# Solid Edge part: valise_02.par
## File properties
Author: Bernard DUMAS
Template: Normal.par
Last saved by: FR026244
Revision: 13
Application: Solid Edge
Material: Bois, Frêne
Style de face: Jaune kaki
Style de remplissage: Liège
Style virtuel: Frêne verni
Coef. of Thermal Exp: 0.0
Thermal Conductivity: 0.0
Specific Heat: 0.0
Modulus of Elasticity: 0.0
Poission's Ratio: 0.0
Yield Stress: 0.0
Ultimate Stress: 0.0
Elongation: 0.0
Densité: 460.000 kg/m^3
Précision: 0.9900
Document Number: 02
Revision: a
Project Name: Slamson
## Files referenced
..\Valise_Salmson.asm
bD:\Documents and Settings\FR026244\Mes Documents\Bernard\Slamson\Valise-Salmson\Valise_Salmson.asm
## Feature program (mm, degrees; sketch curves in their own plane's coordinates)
sketch for "unnamed Protrusion 1" plane through (0, 0, 0) normal (0, -1, 0) x-axis (1, 0, 0)
extrude "unnamed Protrusion 1" add to key point symmetric
extrude "unnamed Cutout 1" cut finite 6
extrude "Enlèvement_matière_2" cut finite 6
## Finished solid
Body 1: solid body, 10 faces, 24 edges, 16 vertices.
  Faces by surface: plane 10
  Edges by curve: line 24
Bounding box of the edges (mm): 6.000 x 850.000 x 103.000, from (0, -425, 3) to (6, 425, 106).
Planar faces by outward normal: +x 3, +y 2, +z 1, -x 1, -y 2, -z 1
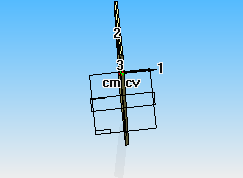
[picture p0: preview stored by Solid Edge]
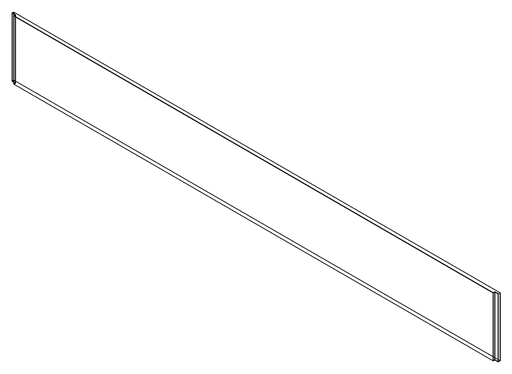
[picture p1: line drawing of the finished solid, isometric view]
